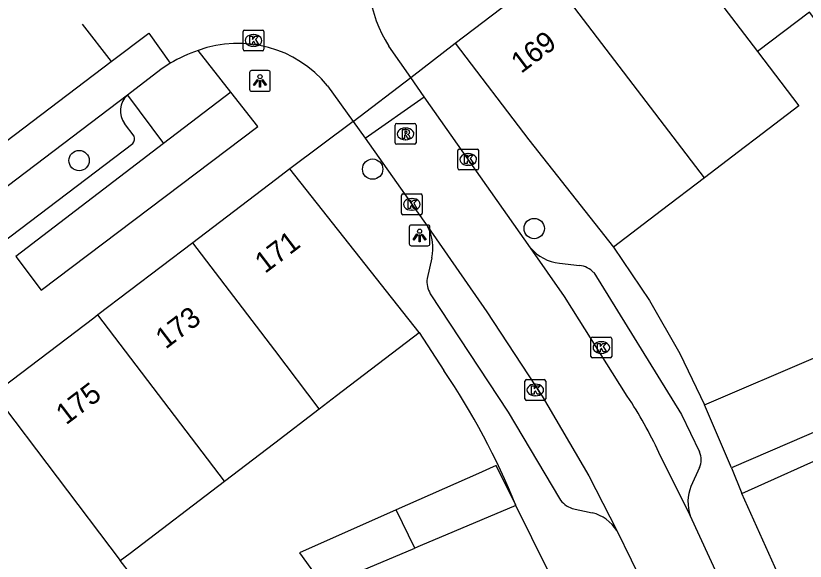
# Model space of a CAD drawing. Extents: x 159377 to 159983, y 382996 to 383595.
# Drawn here: x 159487.55 to 159525.51, y 383455.59 to 383481.82 of the extents above; entities that cross this region are included whole.
import ezdxf

# ---------------------------------------------------------------- set-up
doc = ezdxf.new("R2010")
doc.units = 0
for name, color, linetype in [('IMGEO_Boom', 7, 'Continuous'), ('IMGEO_Groenvoorziening', 7, 'Continuous'), ('IMGEO_Kolk', 7, 'Continuous'), ('IMGEO_Lichtpunt', 7, 'Continuous'), ('IMGEO_Muur', 7, 'Continuous'), ('IMGEO_Pand', 7, 'Continuous'), ('IMGEO_Pand_nummerreeks', 7, 'Continuous'), ('IMGEO_Rijbaan_lokaal_gesloten', 7, 'Continuous'), ('IMGEO_Rijbaan_lokaal_open', 7, 'Continuous'), ('IMGEO_Rijbaan_regionaal_open', 7, 'Continuous'), ('IMGEO_Rioolput', 7, 'Continuous'), ('IMGEO_Voetpad_open', 7, 'Continuous')]:
    doc.layers.add(name, color=color, linetype=linetype)

msp = doc.modelspace()

# ---------------------------------------------------------------- linework, layer by layer
at = {"layer": 'IMGEO_Boom'}
for centre in [(159490.594, 383474.855), (159504.71, 383474.444), (159512.478, 383471.589)]:
    msp.add_circle(centre, 0.489, dxfattribs=at)
at = {"layer": 'IMGEO_Groenvoorziening'}
msp.add_lwpolyline([(159497.887, 383478.152), (159494.651, 383475.67)], dxfattribs=at)
at = {"layer": 'IMGEO_Kolk'}
for p, q in [((159498.481, 383480.205), (159498.481, 383481.057)), ((159498.556, 383481.131), (159499.408, 383481.131)), ((159498.969, 383480.911), (159498.994, 383480.911)), ((159499.482, 383481.057), (159499.482, 383480.205)), ((159499.408, 383480.131), (159498.556, 383480.131)), ((159498.992, 383480.351), (159498.967, 383480.351)), ((159508.807, 383474.486), (159508.807, 383475.338)), ((159508.882, 383475.412), (159509.734, 383475.412)), ((159509.295, 383475.192), (159509.32, 383475.192)), ((159509.808, 383475.338), (159509.808, 383474.486)), ((159509.734, 383474.412), (159508.882, 383474.412)), ((159509.318, 383474.632), (159509.293, 383474.632)), ((159506.169, 383473.252), (159507.021, 383473.252)), ((159506.094, 383472.326), (159506.094, 383473.178)), ((159506.582, 383473.032), (159506.607, 383473.032)), ((159507.095, 383473.178), (159507.095, 383472.326)), ((159506.605, 383472.472), (159506.58, 383472.472)), ((159507.021, 383472.252), (159506.169, 383472.252)), ((159515.207, 383465.44), (159515.207, 383466.292)), ((159515.282, 383466.366), (159516.134, 383466.366)), ((159515.695, 383466.146), (159515.72, 383466.146)), ((159516.208, 383466.292), (159516.208, 383465.44)), ((159516.134, 383465.366), (159515.282, 383465.366)), ((159515.718, 383465.586), (159515.693, 383465.586)), ((159512.03, 383463.4), (159512.03, 383464.252)), ((159512.105, 383464.326), (159512.957, 383464.326)), ((159512.518, 383464.106), (159512.543, 383464.106)), ((159513.031, 383464.252), (159513.031, 383463.4)), ((159512.541, 383463.546), (159512.516, 383463.546)), ((159512.957, 383463.326), (159512.105, 383463.326))]:
    msp.add_line(p, q, dxfattribs=at)
for points in [[(159498.481, 383480.205), (159498.481, 383481.057)], [(159498.556, 383481.131), (159499.408, 383481.131)], [(159498.802, 383480.831), (159498.925, 383480.831), (159498.925, 383480.68), (159499.055, 383480.831), (159499.219, 383480.831), (159499.073, 383480.68), (159499.226, 383480.431), (159499.074, 383480.431), (159498.989, 383480.595), (159498.925, 383480.528), (159498.925, 383480.431), (159498.802, 383480.431), (159498.802, 383480.831)], [(159499.482, 383481.057), (159499.482, 383480.205)], [(159499.408, 383480.131), (159498.556, 383480.131)], [(159508.807, 383474.486), (159508.807, 383475.338)], [(159508.882, 383475.412), (159509.734, 383475.412)], [(159509.808, 383475.338), (159509.808, 383474.486)], [(159509.128, 383475.112), (159509.251, 383475.112), (159509.251, 383474.961), (159509.381, 383475.112), (159509.545, 383475.112), (159509.399, 383474.961), (159509.552, 383474.712), (159509.4, 383474.712), (159509.315, 383474.876), (159509.251, 383474.809), (159509.251, 383474.712), (159509.128, 383474.712), (159509.128, 383475.112)], [(159509.734, 383474.412), (159508.882, 383474.412)], [(159506.169, 383473.252), (159507.021, 383473.252)], [(159506.094, 383472.326), (159506.094, 383473.178)], [(159506.415, 383472.952), (159506.538, 383472.952), (159506.538, 383472.801), (159506.668, 383472.952), (159506.832, 383472.952), (159506.686, 383472.801), (159506.839, 383472.552), (159506.687, 383472.552), (159506.602, 383472.716), (159506.538, 383472.649), (159506.538, 383472.552), (159506.415, 383472.552), (159506.415, 383472.952)], [(159507.095, 383473.178), (159507.095, 383472.326)], [(159507.021, 383472.252), (159506.169, 383472.252)], [(159515.207, 383465.44), (159515.207, 383466.292)], [(159515.282, 383466.366), (159516.134, 383466.366)], [(159515.528, 383466.066), (159515.651, 383466.066), (159515.651, 383465.915), (159515.781, 383466.066), (159515.945, 383466.066), (159515.799, 383465.915), (159515.952, 383465.666), (159515.8, 383465.666), (159515.715, 383465.83), (159515.651, 383465.763), (159515.651, 383465.666), (159515.528, 383465.666), (159515.528, 383466.066)], [(159516.208, 383466.292), (159516.208, 383465.44)], [(159516.134, 383465.366), (159515.282, 383465.366)], [(159512.03, 383463.4), (159512.03, 383464.252)], [(159512.105, 383464.326), (159512.957, 383464.326)], [(159513.031, 383464.252), (159513.031, 383463.4)], [(159512.351, 383464.026), (159512.474, 383464.026), (159512.474, 383463.875), (159512.604, 383464.026), (159512.768, 383464.026), (159512.622, 383463.875), (159512.775, 383463.626), (159512.623, 383463.626), (159512.538, 383463.79), (159512.474, 383463.723), (159512.474, 383463.626), (159512.351, 383463.626), (159512.351, 383464.026)], [(159512.957, 383463.326), (159512.105, 383463.326)]]:
    msp.add_lwpolyline(points, dxfattribs=at)
for centre, start, end in [((159498.558, 383481.055), 91.552, 178.448), ((159498.558, 383481.055), 91.552, 178.448), ((159499.406, 383481.055), 1.552, 88.448), ((159499.406, 383481.055), 1.552, 88.448), ((159498.558, 383480.207), 181.552, 268.448), ((159498.558, 383480.207), 181.552, 268.448), ((159499.406, 383480.207), 271.552, 358.448), ((159499.406, 383480.207), 271.552, 358.448), ((159508.884, 383475.336), 91.552, 178.448), ((159508.884, 383475.336), 91.552, 178.448), ((159509.732, 383475.336), 1.552, 88.448), ((159509.732, 383475.336), 1.552, 88.448), ((159508.884, 383474.488), 181.552, 268.448), ((159508.884, 383474.488), 181.552, 268.448), ((159509.732, 383474.488), 271.552, 358.448), ((159509.732, 383474.488), 271.552, 358.448), ((159506.171, 383473.176), 91.552, 178.448), ((159506.171, 383473.176), 91.552, 178.448), ((159507.019, 383473.176), 1.552, 88.448), ((159507.019, 383473.176), 1.552, 88.448), ((159506.171, 383472.328), 181.552, 268.448), ((159506.171, 383472.328), 181.552, 268.448), ((159507.019, 383472.328), 271.552, 358.448), ((159507.019, 383472.328), 271.552, 358.448), ((159515.284, 383466.29), 91.552, 178.448), ((159515.284, 383466.29), 91.552, 178.448), ((159516.132, 383466.29), 1.552, 88.448), ((159516.132, 383466.29), 1.552, 88.448), ((159515.284, 383465.442), 181.552, 268.448), ((159515.284, 383465.442), 181.552, 268.448), ((159516.132, 383465.442), 271.552, 358.448), ((159516.132, 383465.442), 271.552, 358.448), ((159512.107, 383464.25), 91.552, 178.448), ((159512.107, 383464.25), 91.552, 178.448), ((159512.955, 383464.25), 1.552, 88.448), ((159512.955, 383464.25), 1.552, 88.448), ((159512.107, 383463.402), 181.552, 268.448), ((159512.107, 383463.402), 181.552, 268.448), ((159512.955, 383463.402), 271.552, 358.448), ((159512.955, 383463.402), 271.552, 358.448)]:
    msp.add_arc(centre, 0.0765, start, end, dxfattribs=at)
for centre, major_axis, ratio, start_param, end_param in [((159498.968, 383480.631), (-0.387, 0.002), 0.722429, 4.712389, 7.853982), ((159498.993, 383480.631), (-0.39, 0.002), 0.717154, 1.570796, 4.712389), ((159509.294, 383474.912), (-0.387, 0.002), 0.722429, 4.712389, 7.853982), ((159509.319, 383474.912), (-0.39, 0.002), 0.717154, 1.570796, 4.712389), ((159506.581, 383472.752), (-0.387, 0.002), 0.722429, 4.712389, 7.853982), ((159506.606, 383472.752), (-0.39, 0.002), 0.717154, 1.570796, 4.712389), ((159515.694, 383465.866), (-0.387, 0.002), 0.722429, 4.712389, 7.853982), ((159515.719, 383465.866), (-0.39, 0.002), 0.717154, 1.570796, 4.712389), ((159512.517, 383463.826), (-0.387, 0.002), 0.722429, 4.712389, 7.853982), ((159512.542, 383463.826), (-0.39, 0.002), 0.717154, 1.570796, 4.712389)]:
    msp.add_ellipse(centre, major_axis=major_axis, ratio=ratio, start_param=start_param, end_param=end_param, dxfattribs=at)
at = {"layer": 'IMGEO_Lichtpunt'}
for p, q in [((159498.792, 383479.091), (159498.792, 383478.284)), ((159498.792, 383479.091), (159498.792, 383478.284)), ((159499.694, 383479.186), (159498.886, 383479.186)), ((159499.694, 383479.186), (159498.886, 383479.186)), ((159499.788, 383478.284), (159499.788, 383479.091)), ((159499.788, 383478.284), (159499.788, 383479.091)), ((159498.886, 383478.19), (159499.694, 383478.19)), ((159498.886, 383478.19), (159499.694, 383478.19)), ((159507.371, 383471.757), (159506.563, 383471.757)), ((159507.371, 383471.757), (159506.563, 383471.757)), ((159506.469, 383471.662), (159506.469, 383470.855)), ((159506.469, 383471.662), (159506.469, 383470.855)), ((159507.465, 383470.855), (159507.465, 383471.662)), ((159507.465, 383470.855), (159507.465, 383471.662)), ((159506.563, 383470.761), (159507.371, 383470.761)), ((159506.563, 383470.761), (159507.371, 383470.761))]:
    msp.add_line(p, q, dxfattribs=at)
for points in [[(159499.166, 383478.755), (159499.205, 383478.727), (159499.017, 383478.465), (159498.979, 383478.492), (159499.166, 383478.755)], [(159499.268, 383478.707), (159499.315, 383478.707), (159499.315, 383478.385), (159499.268, 383478.385), (159499.268, 383478.707)], [(159499.378, 383478.727), (159499.416, 383478.754), (159499.603, 383478.492), (159499.564, 383478.464), (159499.378, 383478.727)], [(159506.843, 383471.326), (159506.882, 383471.298), (159506.694, 383471.036), (159506.656, 383471.063), (159506.843, 383471.326)], [(159507.055, 383471.298), (159507.093, 383471.325), (159507.28, 383471.063), (159507.241, 383471.035), (159507.055, 383471.298)], [(159506.945, 383471.278), (159506.992, 383471.278), (159506.992, 383470.956), (159506.945, 383470.956), (159506.945, 383471.278)]]:
    msp.add_lwpolyline(points, dxfattribs=at)
for centre in [(159499.291, 383478.889), (159506.968, 383471.46)]:
    msp.add_circle(centre, 0.0994, dxfattribs=at)
for centre, start, end in [((159498.886, 383479.091), 90, 180), ((159498.886, 383479.091), 90, 180), ((159499.694, 383479.091), 0, 90), ((159499.694, 383479.091), 0, 90), ((159498.886, 383478.284), 180, 270), ((159498.886, 383478.284), 180, 270), ((159499.694, 383478.284), 270, 0), ((159499.694, 383478.284), 270, 360), ((159506.563, 383471.662), 90, 180), ((159506.563, 383471.662), 90, 180), ((159507.371, 383471.662), 0, 90), ((159507.371, 383471.662), 0, 90), ((159506.563, 383470.855), 180, 270), ((159506.563, 383470.855), 180, 270), ((159507.371, 383470.855), 270, 0), ((159507.371, 383470.855), 270, 360)]:
    msp.add_arc(centre, 0.0946, start, end, dxfattribs=at)
at = {"layer": 'IMGEO_Muur'}
for points in [[(159516.285, 383470.688), (159518.024, 383468.125), (159519.475, 383465.583), (159520.663, 383463.106)], [(159506.951, 383466.588), (159508.137, 383464.762)]]:
    msp.add_lwpolyline(points, dxfattribs=at)
msp.add_arc((159478.871, 383444.982), 35.324, 22.1097, 34.0537, dxfattribs=at)
at = {"layer": 'IMGEO_Pand'}
for points in [[(159517.687, 383487.34), (159523.214, 383480.094)], [(159508.68, 383480.507), (159513.142, 383483.892)], [(159520.665, 383474.03), (159513.142, 383483.892)], [(159528.847, 383482.421), (159529.823, 383481.142), (159527.636, 383479.474), (159525.71, 383481.998), (159523.214, 383480.094)], [(159508.68, 383480.507), (159512.213, 383475.86), (159516.285, 383470.688)], [(159523.214, 383480.094), (159525.2, 383477.49), (159523.165, 383475.937), (159522.569, 383475.482), (159520.665, 383474.03)], [(159500.731, 383474.456), (159500.039, 383473.929), (159496.066, 383470.906)], [(159506.951, 383466.588), (159500.731, 383474.456)], [(159520.665, 383474.03), (159518.593, 383472.449), (159516.285, 383470.688)], [(159496.066, 383470.906), (159491.499, 383467.432)], [(159502.144, 383462.921), (159500, 383465.737), (159496.066, 383470.906)], [(159491.499, 383467.432), (159491.306, 383467.285), (159486.499, 383463.639)], [(159497.581, 383459.441), (159491.499, 383467.432)], [(159502.144, 383462.921), (159502.976, 383463.556), (159506.951, 383466.588)], [(159520.663, 383463.106), (159526.129, 383465.459), (159527.431, 383462.436)], [(159522.471, 383458.851), (159527.035, 383460.894), (159529.941, 383462.194), (159534.376, 383464.178)], [(159486.499, 383463.639), (159492.574, 383455.621)], [(159521.965, 383460.082), (159520.663, 383463.106)], [(159497.581, 383459.441), (159500, 383461.286), (159502.144, 383462.921)], [(159527.431, 383462.436), (159521.965, 383460.082)], [(159481.987, 383460.213), (159487.219, 383453.635), (159487.559, 383453.189), (159488.719, 383451.668), (159489.19, 383452.028), (159489.948, 383452.606), (159493.061, 383454.981), (159492.574, 383455.621)], [(159511.597, 383458.277), (159511.591, 383458.286), (159510.65, 383460.19), (159510.327, 383460.047), (159509.793, 383459.81), (159505.845, 383458.058)], [(159492.574, 383455.621), (159493.049, 383455.984), (159497.581, 383459.441)], [(159524.622, 383454.046), (159522.471, 383458.851)], [(159505.845, 383458.058), (159501.187, 383455.992), (159502.363, 383454.381)], [(159506.74, 383456.228), (159505.845, 383458.058)], [(159511.597, 383458.277), (159506.991, 383456.334), (159506.74, 383456.228)], [(159514.663, 383452.079), (159511.597, 383458.277)], [(159502.363, 383454.381), (159506.74, 383456.228)]]:
    msp.add_lwpolyline(points, dxfattribs=at)
at = {"layer": 'IMGEO_Rijbaan_lokaal_gesloten'}
for points in [[(159492.14, 383479.622), (159493.954, 383480.98), (159494.976, 383479.535)], [(159494.976, 383479.535), (159494.529, 383479.229), (159492.914, 383477.993)], [(159492.914, 383477.993), (159477.407, 383466.243)]]:
    msp.add_lwpolyline(points, dxfattribs=at)
at = {"layer": 'IMGEO_Rijbaan_lokaal_open'}
for points in [[(159506.539, 383478.849), (159505.484, 383480.364)], [(159503.767, 383476.741), (159506.539, 383478.849)], [(159507.184, 383477.923), (159506.539, 383478.849)], [(159502.534, 383478.452), (159503.767, 383476.741)], [(159504.352, 383475.93), (159507.184, 383477.923)], [(159512.306, 383470.663), (159507.184, 383477.923)], [(159503.767, 383476.741), (159504.352, 383475.93)], [(159504.352, 383475.93), (159507.358, 383471.672)], [(159507.358, 383471.672), (159510.201, 383467.59), (159512.865, 383463.523), (159515.11, 383459.706), (159516.451, 383457.066)], [(159516.957, 383463.53), (159513.931, 383468.315), (159512.306, 383470.663)], [(159519.986, 383457.784), (159518.479, 383460.814)], [(159524.331, 383448.016), (159522.767, 383451.739), (159519.986, 383457.784)], [(159516.451, 383457.066), (159517.828, 383454.245)]]:
    msp.add_lwpolyline(points, dxfattribs=at)
for centre, radius, start, end in [((159510.502, 383483.605), 5.974, 161.1106, 212.8586), ((159498.242, 383474.961), 5.533, 39.1172, 110.3117), ((159498.541, 383473.516), 6.996, 108.5049, 120.6395), ((159499.298, 383451.85), 21.172, 25.049, 33.4821)]:
    msp.add_arc(centre, radius, start, end, dxfattribs=at)
at = {"layer": 'IMGEO_Rijbaan_regionaal_open'}
for points in [[(159490.734, 383481.412), (159492.14, 383479.622)], [(159424.779, 383428.544), (159434.929, 383436.186), (159492.14, 383479.622)]]:
    msp.add_lwpolyline(points, dxfattribs=at)
at = {"layer": 'IMGEO_Rioolput'}
for p, q in [((159505.869, 383476.639), (159506.721, 383476.639)), ((159505.794, 383475.713), (159505.794, 383476.565)), ((159506.282, 383476.419), (159506.307, 383476.419)), ((159506.795, 383476.565), (159506.795, 383475.713)), ((159506.721, 383475.639), (159505.869, 383475.639)), ((159506.305, 383475.859), (159506.28, 383475.859))]:
    msp.add_line(p, q, dxfattribs=at)
for points in [[(159505.869, 383476.639), (159506.721, 383476.639)], [(159505.794, 383475.713), (159505.794, 383476.565)], [(159506.383, 383476.337), (159506.131, 383476.339), (159506.131, 383475.939)], [(159506.309, 383476.258), (159506.255, 383476.258), (159506.255, 383476.177)], [(159506.795, 383476.565), (159506.795, 383475.713)], [(159506.131, 383475.939), (159506.255, 383475.939), (159506.255, 383476.101), (159506.266, 383476.101)], [(159506.255, 383476.177), (159506.307, 383476.177)], [(159506.313, 383476.072), (159506.384, 383475.939), (159506.524, 383475.939), (159506.459, 383476.065)], [(159506.721, 383475.639), (159505.869, 383475.639)]]:
    msp.add_lwpolyline(points, dxfattribs=at)
for centre, radius, start, end in [((159505.871, 383476.563), 0.0765, 91.552, 178.448), ((159505.871, 383476.563), 0.0765, 91.552, 178.448), ((159506.719, 383476.563), 0.0765, 1.552, 88.448), ((159506.719, 383476.563), 0.0765, 1.552, 88.448), ((159506.315, 383476.162), 0.0964, 77.0061, 93.1865), ((159506.329, 383476.219), 0.0378, 276.6634, 79.6772), ((159506.382, 383476.227), 0.109, 350.3612, 89.416), ((159506.265, 383476.048), 0.0533, 26.0293, 88.6989), ((159506.291, 383476.366), 0.19, 274.7715, 282.9687), ((159506.38, 383476.227), 0.112, 277.5842, 350.9817), ((159506.364, 383476.012), 0.108, 29.5134, 73.7905), ((159505.871, 383475.715), 0.0765, 181.552, 268.448), ((159505.871, 383475.715), 0.0765, 181.552, 268.448), ((159506.719, 383475.715), 0.0765, 271.552, 358.448), ((159506.719, 383475.715), 0.0765, 271.552, 358.448)]:
    msp.add_arc(centre, radius, start, end, dxfattribs=at)
for centre, major_axis, ratio, start_param, end_param in [((159506.281, 383476.139), (-0.387, 0.002), 0.722429, 4.712389, 7.853982), ((159506.306, 383476.139), (-0.39, 0.002), 0.717154, 1.570796, 4.712389)]:
    msp.add_ellipse(centre, major_axis=major_axis, ratio=ratio, start_param=start_param, end_param=end_param, dxfattribs=at)
at = {"layer": 'IMGEO_Voetpad_open'}
for points in [[(159506.539, 383478.849), (159508.68, 383480.507)], [(159497.887, 383478.152), (159496.321, 383480.15)], [(159494.651, 383475.67), (159487.555, 383470.245), (159488.769, 383468.626), (159499.19, 383476.49), (159497.887, 383478.152)], [(159492.914, 383477.993), (159494.651, 383475.67)], [(159493.24, 383476.031), (159492.772, 383476.635)], [(159503.767, 383476.741), (159500.731, 383474.456)], [(159479.198, 383465.082), (159493.171, 383475.68)], [(159516.285, 383470.688), (159518.024, 383468.125), (159519.475, 383465.583), (159520.663, 383463.106)], [(159507.562, 383470.179), (159507.328, 383469.184)], [(159513.69, 383469.92), (159514.662, 383469.819)], [(159515.339, 383469.467), (159519.564, 383462.655), (159520.424, 383460.847)], [(159507.483, 383468.454), (159511.23, 383462.753), (159513.691, 383458.604)], [(159506.951, 383466.588), (159508.137, 383464.762)], [(159520.431, 383460.094), (159520.016, 383459.193)], [(159521.965, 383460.082), (159522.471, 383458.851)], [(159514.301, 383458.134), (159515.271, 383457.918)]]:
    msp.add_lwpolyline(points, dxfattribs=at)
for centre, radius, start, end in [((159493.594, 383477.235), 1.018, 131.9285, 216.1326), ((159492.923, 383475.911), 0.339, 316.9906, 20.7665), ((159505.381, 383470.641), 2.229, 348.0283, 27.5329), ((159513.924, 383472.016), 2.109, 219.9103, 263.6315), ((159514.527, 383468.733), 1.094, 42.1264, 82.9301), ((159508.424, 383469.035), 1.106, 172.2791, 211.6959), ((159478.871, 383444.982), 35.324, 22.1097, 34.0537), ((159519.599, 383460.463), 0.91, 336.1049, 24.9604), ((159521.845, 383458.449), 1.974, 157.871, 199.6895), ((159514.681, 383459.258), 1.187, 213.4526, 251.3195), ((159514.821, 383456.051), 1.92, 31.9017, 76.4372)]:
    msp.add_arc(centre, radius, start, end, dxfattribs=at)

# ---------------------------------------------------------------- texts
at = {"layer": 'IMGEO_Pand_nummerreeks'}
for s, rotation, p in [('169', 37.0131, (159511.848, 383479.015)), ('171', 37.2881, (159499.533, 383469.398)), ('173', 37.2709, (159494.757, 383465.763)), ('175', 37.2594, (159489.968, 383462.118))]:
    msp.add_text(s, height=1, rotation=rotation, dxfattribs=at).set_placement(p)

doc.saveas('drawing.dxf')
